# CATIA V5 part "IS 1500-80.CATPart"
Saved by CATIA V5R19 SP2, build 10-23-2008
Part number: IS 1500-80
Bounding box of the stored display mesh (mm): x -37.351 to 37.351, y -37.351 to 37.351, z 0 to 270
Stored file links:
  C:\Users\Bora\Desktop\3D Katı model\IS serisi\IS 1500\IS 1500-80.CATPart
  C:\Program Files\Dassault Systemes\B19\intel_a\reffiles\standard\MetricThickPitch.txt
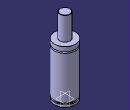
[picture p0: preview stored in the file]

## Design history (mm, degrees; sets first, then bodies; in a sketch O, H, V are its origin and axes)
Body1 (main body)
  Sketch1 on yz-plane, origin (0, 0, 0), H (0, 1, 0), V (0, 0, 1)
    point P1 (37.5, 171.5)
    point P2 (37.5, 166.5)
    point P5 (18, 269)
    point P7 (18, 269)
    point P12 (37.5, 166.5)
    point P13 (37.5, 171.5)
    arc A1 centre (37.5, 169) radius 2.5 from (37.5, 171.5) to (37.5, 166.5) ccw
    line L1 (37.5, 0) -> (37.5, 8)
    line L2 (18, 269) -> (18, 187)
    arc A2 centre (17, 269) radius 1 from (18, 269) to (17, 270) ccw
    line L3 (33.5, 13) -> (33.5, 8)
    line L4 (37.5, 13) -> (37.5, 166.5)
    line L5 (37.5, 171.5) -> (37.5, 187)
    line L6 (17, 270) -> (0, 270)
    point P15 (0, 270)
    line L7 (18, 187) -> (37.5, 187)
    line L8 (0, 0) -> (37.5, 0)
    line L9 (33.5, 8) -> (37.5, 8)
    line L10 (33.5, 13) -> (37.5, 13)
    coincidence: P15 V, P1 P13, P2 P12, P5 P7
    tangency: L6 A2
    horizontal: L7 H, L8 H, L9 H, L10 H
  Shaft1: profile Sketch1, axis Sketch1.V, angle 360
  Sketch2 on face of Shaft1 from Sketch1.L8, origin (0, 0, 0), H (1, 0, 0), V (0, -1, 0)
    point P1 (20, 0)
    distance P1 V = 20
  Hole1: placed by Sketch2, at (20, 0, 0) direction (0, 0, 1), diameter 6.647, depth 13, threaded "M8", thread diameter 8, thread depth 13, pitch 1.25
  CircPattern1: of Hole1, instances 4, angular step 90, axis from xy-plane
